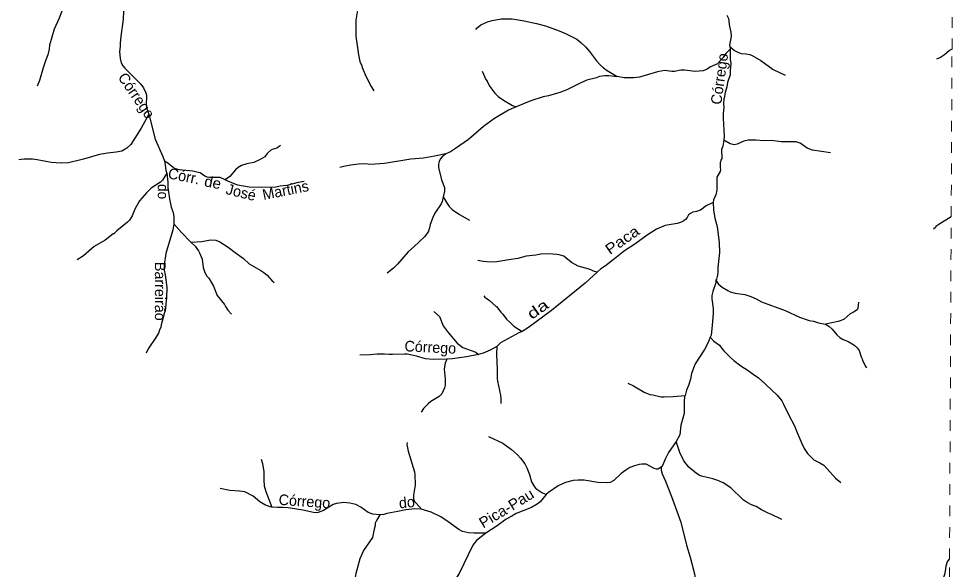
# Model space of a CAD drawing. Extents: x 551.6 to 577.6, y 7567 to 7594.7.
# Drawn here: x 568.78 to 577.56, y 7579.74 to 7584.89 of the extents above; entities that cross this region are included whole.
import ezdxf
from ezdxf.enums import TextEntityAlignment as Align

# ---------------------------------------------------------------- set-up
doc = ezdxf.new("R2010")
doc.units = 0
doc.header["$LTSCALE"] = 0.04
doc.linetypes.add('SHORT_DASHED', pattern=[2.7, 1.5, -1.2])
doc.layers.add('53', color=7, linetype='SHORT_DASHED', lineweight=13)
doc.layers.add('7', color=7, linetype='Continuous', lineweight=25)
doc.layers.add('61', color=7, linetype='Continuous')

msp = doc.modelspace()

# ---------------------------------------------------------------- linework, layer by layer
at = {"layer": '53'}
msp.add_lwpolyline([(577.4204, 7566.9518), (577.4226, 7567.3928), (577.4384, 7570.6314), (577.4446, 7571.9213), (577.4462, 7572.242), (577.4659, 7576.2813), (577.4696, 7577.0412), (577.4755, 7578.252), (577.4832, 7579.8317), (577.4989, 7583.0336), (577.5065, 7584.6034), (577.518, 7586.9644), (577.5184, 7587.0352), (577.519, 7587.1599), (577.5202, 7587.417), (577.5286, 7589.1281), (577.5292, 7589.2596), (577.5446, 7592.4063), (577.549, 7593.3187), (577.5554, 7594.6251)], dxfattribs=at)
at = {"layer": '7'}
for points in [[(571.9926, 7585.1972), (571.9443, 7584.9686), (571.9306, 7584.8736), (571.929, 7584.7256), (571.9547, 7584.5501), (571.9676, 7584.4873), (571.9861, 7584.4479), (571.9893, 7584.4326), (572.0264, 7584.3441), (572.0738, 7584.2547), (572.0964, 7584.2129)], [(569.7609, 7585.0958), (569.7528, 7584.8849), (569.7303, 7584.7207), (569.7246, 7584.6612), (569.7246, 7584.6274), (569.7182, 7584.5823), (569.723, 7584.5147), (569.7335, 7584.4761), (569.7496, 7584.4471), (569.7673, 7584.4237), (569.9162, 7584.2749), (569.9435, 7584.2411), (569.9653, 7584.1928), (569.9693, 7584.1735), (569.9717, 7584.1541), (569.9661, 7584.0898), (569.9741, 7584.0447), (569.9933, 7583.9944)], [(569.179, 7584.9573), (569.1548, 7584.8929), (569.1082, 7584.7915), (569.0631, 7584.6402), (569.0599, 7584.6032), (569.0486, 7584.5485), (569.0293, 7584.5034), (569.0027, 7584.4278), (568.9689, 7584.3087), (568.9488, 7584.258)], [(573.0525, 7584.7875), (573.0654, 7584.8028), (573.1, 7584.8293), (573.1595, 7584.8575), (573.2046, 7584.872), (573.2883, 7584.8865), (573.3913, 7584.8865), (573.504, 7584.8688), (573.6183, 7584.843), (573.702, 7584.8205), (573.8324, 7584.7746), (573.8967, 7584.7473), (573.9957, 7584.6958), (574.0344, 7584.6652), (574.0778, 7584.6233), (574.1148, 7584.5807), (574.1816, 7584.4929)], [(575.3989, 7584.9221), (575.4146, 7584.8913), (575.4194, 7584.8688), (575.421, 7584.835), (575.4266, 7584.8012), (575.4379, 7584.761), (575.4419, 7584.7223), (575.425, 7584.6419), (575.427, 7584.6289), (575.4307, 7584.6044)], [(575.427, 7584.6289), (575.4709, 7584.5911), (575.5096, 7584.5702), (575.5353, 7584.563), (575.5804, 7584.5597), (575.6142, 7584.5525), (575.6367, 7584.5428), (575.7188, 7584.4978), (575.8338, 7584.4124), (575.9466, 7584.3602)], [(575.4307, 7584.6044), (575.3912, 7584.563), (575.3661, 7584.5249), (575.3132, 7584.4664), (575.248, 7584.4374), (575.2166, 7584.4157), (575.178, 7584.4004), (575.1039, 7584.394), (575.0041, 7584.4068), (574.9703, 7584.4068), (574.9092, 7584.394), (574.8866, 7584.394), (574.819, 7584.4036), (574.7514, 7584.3907), (574.5824, 7584.3408), (574.5261, 7584.336), (574.4392, 7584.3344), (574.3742, 7584.3461)], [(575.4307, 7584.6044), (575.4323, 7584.505), (575.4387, 7584.4761), (575.4355, 7584.4278)], [(577.5065, 7584.6034), (577.4829, 7584.5895), (577.4354, 7584.5493), (577.3992, 7584.5243), (577.363, 7584.5083)], [(574.1816, 7584.4929), (574.2162, 7584.4551), (574.2476, 7584.4286), (574.2814, 7584.4036), (574.3742, 7584.3461)], [(573.1104, 7584.3964), (573.145, 7584.3199), (573.1563, 7584.3046), (573.1563, 7584.2998), (573.1837, 7584.2523), (573.2303, 7584.1896), (573.2601, 7584.1614), (573.3092, 7584.1244), (573.3945, 7584.0769), (573.4294, 7584.0619)], [(574.3742, 7584.3461), (574.349, 7584.3457), (574.2975, 7584.3537), (574.2589, 7584.3537), (574.2074, 7584.3457), (574.1816, 7584.336), (574.0915, 7584.3119), (574.0263, 7584.2845), (573.9032, 7584.2225), (573.8388, 7584.196), (573.7326, 7584.1654), (573.681, 7584.1573), (573.5652, 7584.1203), (573.4294, 7584.0619)], [(575.4355, 7584.4278), (575.4299, 7584.4085), (575.4299, 7584.3634), (575.4057, 7584.2918), (575.4001, 7584.2507), (575.384, 7584.196), (575.3759, 7584.1429), (575.3727, 7584.1397), (575.3695, 7584.0898), (575.3711, 7584.056), (575.3647, 7583.9996), (575.3647, 7583.9578), (575.3759, 7583.7888), (575.3733, 7583.75)], [(569.9933, 7583.9944), (569.9218, 7583.8644), (569.8228, 7583.7099), (569.7858, 7583.6753), (569.7391, 7583.6495), (569.6876, 7583.6382), (569.6072, 7583.6302), (569.5315, 7583.6165), (569.3802, 7583.5739), (569.2402, 7583.5393), (569.171, 7583.5368), (569.0776, 7583.5417), (568.9488, 7583.5682), (568.9038, 7583.5731)], [(569.9933, 7583.9944), (570.053, 7583.7614), (570.1238, 7583.5972), (570.1386, 7583.5553)], [(573.4294, 7584.0619), (573.3575, 7584.031), (573.2279, 7583.9553), (573.1249, 7583.8789)], [(573.1249, 7583.8789), (572.9825, 7583.759), (572.8626, 7583.672), (572.8154, 7583.6437), (572.7703, 7583.6234)], [(575.3733, 7583.75), (575.3623, 7583.6954), (575.3502, 7583.6648), (575.3518, 7583.5787), (575.3454, 7583.569), (575.3389, 7583.5401), (575.3389, 7583.491)], [(576.3683, 7583.6334), (576.2017, 7583.6584), (576.1518, 7583.6777), (576.0874, 7583.7227), (576.0488, 7583.7372), (575.9071, 7583.7348), (575.817, 7583.7469), (575.7494, 7583.7461), (575.6721, 7583.7517), (575.5981, 7583.7501), (575.5595, 7583.7421), (575.4951, 7583.7147), (575.4693, 7583.7083), (575.4307, 7583.7179), (575.3733, 7583.75)], [(571.2256, 7583.7018), (571.1894, 7583.6769), (571.1475, 7583.6648), (571.1347, 7583.6576), (571.1008, 7583.6278), (571.0767, 7583.5964), (571.0349, 7583.569), (570.9737, 7583.5433), (570.9093, 7583.5288), (570.861, 7583.5135), (570.8288, 7583.4966), (570.8023, 7583.4725), (570.7491, 7583.4113), (570.7053, 7583.3808)], [(568.9038, 7583.5731), (568.8249, 7583.5723), (568.7758, 7583.5682)], [(570.1386, 7583.5553), (570.1463, 7583.52), (570.1528, 7583.4668), (570.1613, 7583.4419)], [(570.2212, 7583.4966), (570.1713, 7583.5352), (570.1386, 7583.5553)], [(572.7703, 7583.6234), (572.6638, 7583.6004), (572.5608, 7583.5835), (572.4449, 7583.5731), (572.197, 7583.5336), (572.1101, 7583.5256), (572.0586, 7583.5248), (572.0199, 7583.5296), (571.9556, 7583.5264), (571.8815, 7583.5167), (571.8171, 7583.5046), (571.7793, 7583.4942)], [(572.7703, 7583.6234), (572.7354, 7583.594), (572.7185, 7583.5731), (572.7088, 7583.5505), (572.704, 7583.528), (572.7032, 7583.4942), (572.7314, 7583.3815), (572.7571, 7583.3091), (572.7587, 7583.2753), (572.7468, 7583.2204)], [(570.7053, 7583.3808), (570.6614, 7583.4016), (570.56, 7583.4032), (570.5375, 7583.4065), (570.515, 7583.4145), (570.4739, 7583.4443), (570.4554, 7583.4499), (570.4039, 7583.462), (570.2767, 7583.4741), (570.2429, 7583.4845), (570.2212, 7583.4966)], [(575.3389, 7583.491), (575.3405, 7583.4797), (575.3373, 7583.4572), (575.3075, 7583.4057), (575.3051, 7583.3815), (575.3067, 7583.285), (575.2955, 7583.2399), (575.2761, 7583.1932), (575.2727, 7583.168)], [(570.1613, 7583.4419), (570.119, 7583.3775), (570.1029, 7583.359), (570.0144, 7583.3018), (569.9709, 7583.2592), (569.9041, 7583.1836), (569.8623, 7583.1047), (569.8365, 7583.0419), (569.8116, 7583.0041), (569.7939, 7582.9855), (569.6924, 7582.9027), (569.6651, 7582.8753), (569.6603, 7582.8745), (569.583, 7582.8157), (569.4816, 7582.7578), (569.381, 7582.6685), (569.3214, 7582.6323)], [(570.1613, 7583.4419), (570.1697, 7583.359), (570.1705, 7583.3075), (570.185, 7583.2029), (570.2019, 7583.1256), (570.2212, 7583.0741), (570.2276, 7583.0355), (570.2277, 7582.9696)], [(571.4445, 7583.3638), (571.3906, 7583.3558), (571.2844, 7583.3284), (571.22, 7583.3212), (571.1813, 7583.3131), (571.0494, 7583.3075), (570.9302, 7583.3131), (570.8256, 7583.3308), (570.7226, 7583.3694), (570.7053, 7583.3808)], [(572.7468, 7583.2204), (572.7378, 7583.1787), (572.7273, 7583.1562), (572.6694, 7583.0677), (572.6485, 7583.029), (572.6251, 7582.9614), (572.6195, 7582.9325)], [(572.7468, 7583.2204), (572.7829, 7583.1578), (572.8038, 7583.1304), (572.8312, 7583.1031), (572.8996, 7583.0548), (572.9913, 7583.0033)], [(575.2727, 7583.168), (575.2053, 7583.1369), (575.1538, 7583.0958), (575.1152, 7583.0837), (575.0822, 7583.0773), (575.0605, 7583.066), (575.0419, 7583.0516), (575.0299, 7583.029), (575.0146, 7583.0105), (574.9969, 7582.996), (574.9671, 7582.9799), (574.9349, 7582.9711), (574.8239, 7582.9526), (574.7426, 7582.9172), (574.654, 7582.8616), (574.5406, 7582.7779), (574.4424, 7582.7143), (574.3635, 7582.654)], [(575.2727, 7583.168), (575.2745, 7583.0999), (575.289, 7583.0226), (575.3083, 7582.9437), (575.3293, 7582.7892), (575.3309, 7582.6991), (575.3164, 7582.559), (575.3148, 7582.5091), (575.3083, 7582.4753)], [(577.4989, 7583.0336), (577.3847, 7582.9638), (577.3558, 7582.9421), (577.3509, 7582.9332), (577.334, 7582.9172)], [(570.2277, 7582.9696), (570.2164, 7582.9115), (570.2043, 7582.8697)], [(570.2277, 7582.9696), (570.2969, 7582.8866), (570.3868, 7582.7977)], [(570.2043, 7582.8697), (570.1528, 7582.6894), (570.1351, 7582.5848), (570.1375, 7582.5365), (570.1463, 7582.4914), (570.1608, 7582.3739), (570.1592, 7582.2774), (570.1504, 7582.221), (570.1471, 7582.1727), (570.1077, 7582.0246), (570.1037, 7582.0005), (570.0932, 7581.9731)], [(572.6195, 7582.9325), (572.6082, 7582.9003), (572.5736, 7582.8503), (572.473, 7582.7538), (572.4183, 7582.7063), (572.3201, 7582.5896), (572.2807, 7582.5526), (572.2219, 7582.5075)], [(570.3868, 7582.7977), (570.4876, 7582.8029), (570.5697, 7582.8182), (570.618, 7582.8157), (570.6582, 7582.8005), (570.7347, 7582.7514), (570.8007, 7582.699), (570.8779, 7582.6443), (570.931, 7582.5936), (571.0413, 7582.5325), (571.0695, 7582.5123), (571.0984, 7582.4882), (571.1435, 7582.4391), (571.166, 7582.419)], [(570.3868, 7582.7977), (570.4248, 7582.7602), (570.4562, 7582.7168), (570.4675, 7582.6958), (570.49, 7582.6379), (570.5021, 7582.5606), (570.5149, 7582.522), (570.5335, 7582.4834), (570.5528, 7582.4592), (570.5978, 7582.3852), (570.6308, 7582.2983), (570.7001, 7582.2146), (570.7097, 7582.1937), (570.7322, 7582.1606), (570.7669, 7582.122)], [(574.1871, 7582.5159), (574.1623, 7582.522), (574.1124, 7582.5437), (574.0086, 7582.5727), (573.9474, 7582.6081), (573.8742, 7582.6652), (573.8324, 7582.6797), (573.8098, 7582.683), (573.7358, 7582.6878), (573.6585, 7582.6862), (573.6134, 7582.6765), (573.5233, 7582.6652), (573.4444, 7582.6427), (573.3607, 7582.6331), (573.2481, 7582.6129), (573.1901, 7582.6089), (573.1193, 7582.617), (573.0718, 7582.625)], [(574.3635, 7582.654), (574.2661, 7582.5767), (574.2202, 7582.5461), (574.1871, 7582.5159)], [(574.1871, 7582.5159), (574.0746, 7582.4133), (573.7583, 7582.1582), (573.5458, 7581.9989), (573.4851, 7581.9612), (573.4541, 7581.9482)], [(575.2978, 7582.4415), (575.2979, 7582.4158), (575.2689, 7582.3369), (575.26, 7582.2983), (575.2584, 7582.2677), (575.2713, 7582.1776), (575.2713, 7582.1325), (575.2633, 7582.0182), (575.252, 7581.9281), (575.2436, 7581.9075)], [(575.3083, 7582.4753), (575.3043, 7582.4512), (575.2978, 7582.4415)], [(575.2978, 7582.4415), (575.322, 7582.4045), (575.355, 7582.3771), (575.4081, 7582.3441), (575.4323, 7582.3329), (575.4774, 7582.32), (575.5675, 7582.3079), (575.6254, 7582.2886), (575.6753, 7582.2669), (575.7236, 7582.2387), (575.9458, 7582.1566), (576.081, 7582.0938), (576.1711, 7582.0649), (576.2113, 7582.0568), (576.2578, 7582.0428), (576.3231, 7582.0312)], [(573.1265, 7582.2959), (573.1362, 7582.2838), (573.1796, 7582.2508), (573.2432, 7582.1936), (573.2465, 7582.1936), (573.2859, 7582.1421), (573.3044, 7582.1236), (573.3382, 7582.0762), (573.3752, 7582.0407), (573.4074, 7582.0118), (573.4851, 7581.9612)], [(576.6331, 7582.2347), (576.6266, 7582.1808), (576.6186, 7582.163), (576.5864, 7582.1421), (576.5542, 7582.126), (576.4986, 7582.0769), (576.4697, 7582.0633), (576.4415, 7582.0552), (576.3231, 7582.0312)], [(572.6598, 7582.1478), (572.7104, 7582.1019), (572.7475, 7582.015), (572.7933, 7581.9522), (572.8762, 7581.8524), (572.9294, 7581.8113), (573.0533, 7581.7671), (573.0779, 7581.7465)], [(576.3231, 7582.0312), (576.3554, 7582.0101), (576.386, 7581.9828)], [(576.386, 7581.9828), (576.4294, 7581.9289), (576.456, 7581.9039), (576.4818, 7581.8894), (576.5365, 7581.8669), (576.588, 7581.8363), (576.6041, 7581.825), (576.6194, 7581.8089), (576.6395, 7581.7848), (576.6556, 7581.7253), (576.6668, 7581.7051), (576.6701, 7581.6898), (576.699, 7581.6319), (576.7079, 7581.6198)], [(570.0932, 7581.9731), (570.0828, 7581.9442), (570.0594, 7581.9047), (569.9854, 7581.7977), (569.9677, 7581.7582)], [(573.4541, 7581.9482), (573.2841, 7581.8536), (573.2468, 7581.821)], [(575.2436, 7581.9075), (575.2238, 7581.8589), (575.1916, 7581.7929), (575.1023, 7581.6577), (575.0685, 7581.5675), (575.0596, 7581.5144), (575.042, 7581.4565)], [(575.2436, 7581.9075), (575.2786, 7581.8709), (575.3309, 7581.8331), (575.3534, 7581.8009), (575.3719, 7581.7808), (575.4339, 7581.7172), (575.4653, 7581.6898), (575.5313, 7581.6399), (575.6005, 7581.5957), (575.6464, 7581.5611), (575.6971, 7581.5281), (575.755, 7581.4758), (575.7671, 7581.4605), (575.8717, 7581.3663), (575.9135, 7581.3116), (575.9313, 7581.281), (575.9787, 7581.1796), (576.0327, 7581.0782), (576.0552, 7581.0235)], [(573.2468, 7581.821), (573.1869, 7581.7856), (573.1193, 7581.7598), (573.1192, 7581.7574), (573.0779, 7581.7465)], [(573.2468, 7581.821), (573.2448, 7581.7494), (573.2529, 7581.6045), (573.2521, 7581.5224), (573.2545, 7581.4951), (573.2818, 7581.3663), (573.2859, 7581.3325), (573.2843, 7581.2987), (573.2867, 7581.2866)], [(572.2726, 7581.7462), (572.2405, 7581.7446), (572.197, 7581.7494), (572.1294, 7581.7502), (572.0618, 7581.7429), (571.9676, 7581.7381)], [(572.7812, 7581.703), (572.6541, 7581.6979), (572.5801, 7581.7051), (572.498, 7581.7301), (572.4079, 7581.7486), (572.3853, 7581.7502), (572.2726, 7581.7462)], [(573.0779, 7581.7465), (572.9632, 7581.7244), (572.833, 7581.7051), (572.7812, 7581.703)], [(572.7812, 7581.703), (572.766, 7581.6657), (572.7571, 7581.6319), (572.7563, 7581.6094), (572.7652, 7581.516), (572.766, 7581.4581), (572.7587, 7581.4355), (572.7322, 7581.3776), (572.7089, 7581.3526), (572.6316, 7581.3059), (572.605, 7581.2842), (572.5615, 7581.2408), (572.5398, 7581.2078)], [(574.4738, 7581.479), (574.5277, 7581.4524), (574.6259, 7581.3937), (574.679, 7581.3711), (574.708, 7581.3679), (574.7868, 7581.3502), (574.8126, 7581.3494), (574.8979, 7581.3518), (575.0089, 7581.3629)], [(575.042, 7581.4565), (575.0234, 7581.413), (575.0089, 7581.3629)], [(575.0089, 7581.3629), (575.0041, 7581.3567), (574.9993, 7581.3019), (575.0009, 7581.1941), (574.9711, 7581.0846), (574.9607, 7580.9945), (574.9244, 7580.9318)], [(576.0552, 7581.0235), (576.1019, 7580.9124), (576.1244, 7580.8673), (576.1542, 7580.8198), (576.2129, 7580.7611), (576.2709, 7580.7321), (576.3063, 7580.7088), (576.3401, 7580.6774), (576.4174, 7580.5897), (576.4665, 7580.5486)], [(572.4079, 7580.9213), (572.4078, 7580.9028), (572.4175, 7580.8416), (572.477, 7580.6484), (572.4811, 7580.6227), (572.4835, 7580.5237), (572.4674, 7580.4295), (572.4698, 7580.3909), (572.4786, 7580.3716), (572.5347, 7580.3105), (572.5402, 7580.2987)], [(573.1716, 7580.9776), (573.3036, 7580.9156), (573.3841, 7580.8569), (573.4428, 7580.8062), (573.471, 7580.7764), (573.5104, 7580.7241), (573.5297, 7580.6855), (573.5547, 7580.6227), (573.574, 7580.5551), (573.6005, 7580.5068), (573.6126, 7580.4923), (573.64, 7580.4722), (573.6682, 7580.4553), (573.7096, 7580.4363)], [(574.9244, 7580.9318), (574.8544, 7580.8287), (574.8255, 7580.7724), (574.7981, 7580.708), (574.786, 7580.6903)], [(575.046, 7580.6911), (575.0081, 7580.737), (574.9953, 7580.7579), (574.9607, 7580.8303), (574.9244, 7580.9318)], [(571.0445, 7580.7651), (571.055, 7580.7273), (571.0695, 7580.6484), (571.067, 7580.5712), (571.0711, 7580.5181), (571.0872, 7580.4633), (571.1419, 7580.3179)], [(574.786, 7580.6903), (574.7547, 7580.6742), (574.7434, 7580.6742), (574.7192, 7580.679), (574.6452, 7580.72), (574.6033, 7580.7208), (574.5808, 7580.7176), (574.5357, 7580.7048), (574.4939, 7580.687), (574.4537, 7580.6645), (574.4102, 7580.6323), (574.3418, 7580.5663), (574.3088, 7580.5486), (574.2863, 7580.5454), (574.1945, 7580.5486), (574.0657, 7580.5695), (574.0094, 7580.5712), (573.9627, 7580.5679), (573.8903, 7580.5478), (573.8227, 7580.5156), (573.7325, 7580.4561), (573.7096, 7580.4363)], [(574.786, 7580.6903), (574.7852, 7580.6629), (574.7957, 7580.6291), (574.8255, 7580.5615), (574.8818, 7580.4167)], [(575.9144, 7580.201), (575.8178, 7580.25), (575.7864, 7580.2621), (575.7244, 7580.2927), (575.6729, 7580.3241), (575.6303, 7580.3394), (575.59, 7580.3611), (575.5538, 7580.3869), (575.4379, 7580.4971), (575.3647, 7580.5454), (575.3148, 7580.5671), (575.2681, 7580.5824), (575.1619, 7580.6082), (575.1426, 7580.6154), (575.1152, 7580.6323), (575.046, 7580.6911)], [(571.1419, 7580.3179), (571.1266, 7580.3192), (571.0767, 7580.3402), (571.0324, 7580.3683), (570.9673, 7580.419), (570.8916, 7580.4609), (570.8417, 7580.4681), (570.75, 7580.4738), (570.6606, 7580.4907)], [(573.7096, 7580.4363), (573.6529, 7580.3683), (573.6247, 7580.345), (573.5732, 7580.3128), (573.4299, 7580.2573), (573.3873, 7580.2339), (573.3366, 7580.205), (573.2513, 7580.143), (573.1451, 7580.075)], [(574.8818, 7580.4167), (574.9687, 7580.1784), (575.0234, 7579.9611), (575.0572, 7579.8501), (575.0967, 7579.6939), (575.1136, 7579.5732), (575.1152, 7579.4944), (575.1196, 7579.461)], [(571.4324, 7580.2887), (571.2972, 7580.3104), (571.2425, 7580.3152), (571.1961, 7580.3134), (571.1419, 7580.3179)], [(572.1544, 7580.2464), (572.0892, 7580.2525), (572.0433, 7580.2669), (571.9749, 7580.3176), (571.9298, 7580.341), (571.8735, 7580.3539), (571.8171, 7580.3603), (571.7495, 7580.353), (571.7173, 7580.3434), (571.6272, 7580.2871), (571.5757, 7580.2661), (571.5644, 7580.2645), (571.5322, 7580.2677), (571.4324, 7580.2887)], [(572.1544, 7580.2464), (572.1221, 7580.1929), (572.1109, 7580.1663), (572.1101, 7580.1462), (572.1004, 7580.1124), (572.0859, 7580.0336), (572.0014, 7579.9128), (571.9676, 7579.834), (571.9298, 7579.6972), (571.9201, 7579.64)], [(572.5402, 7580.2987), (572.4803, 7580.3015), (572.3982, 7580.2935), (572.3209, 7580.2758), (572.2179, 7580.2573), (572.1909, 7580.2495), (572.1544, 7580.2464)], [(573.1451, 7580.075), (573.0372, 7580.0738), (572.9841, 7580.077), (572.9278, 7580.0899), (572.8915, 7580.1084), (572.7933, 7580.1816), (572.7249, 7580.2259), (572.6348, 7580.2702), (572.5402, 7580.2987)], [(573.1451, 7580.075), (573.0573, 7580.0054), (573.0251, 7579.9611), (572.8972, 7579.6955), (572.8778, 7579.6682), (572.8263, 7579.5813), (572.7764, 7579.5201), (572.7394, 7579.463)], [(577.4832, 7579.8317), (577.4757, 7579.8275), (577.4604, 7579.805), (577.4475, 7579.7664), (577.4427, 7579.7181), (577.4354, 7579.6859), (577.3895, 7579.5443), (577.3614, 7579.4774), (577.3517, 7579.4622), (577.3236, 7579.4348), (577.289, 7579.3744), (577.2535, 7579.339), (577.2238, 7579.3157), (577.1666, 7579.2786), (577.1232, 7579.2577)]]:
    msp.add_lwpolyline(points, dxfattribs=at)

# ---------------------------------------------------------------- texts
at = {"layer": '61'}
for s, rotation, p in [('Córrego', 82.134, (575.38, 7584.3186)), ('Córrego', 304.6, (569.8353, 7584.1402)), ('Córr.', 348.474, (570.3111, 7583.3659)), ('José', 346.245, (570.8442, 7583.2152)), ('Martins', 11.31, (571.2808, 7583.2338)), ('Barreirão', 270, (570.0494, 7582.3372)), ('Córrego', 357.245, (572.6239, 7581.7644)), ('Córrego', 355.996, (571.4453, 7580.3227)), ('do', 5.69, (572.4109, 7580.3126))]:
    msp.add_text(s, height=0.1, rotation=rotation, dxfattribs=at).set_placement(p, align=Align.CENTER)
for s, rotation, width, p in [('de', 348.706, 1.05, (570.5815, 7583.3066)), ('do', 270, 0.95, (570.0764, 7583.2702)), ('Paca', 35.24, 1.15, (574.4498, 7582.7761)), ('da', 35.24, 1.4, (573.6598, 7582.129)), ('Pica-Pau', 31.178, 1.05, (573.3637, 7580.2647))]:
    msp.add_text(s, height=0.1, rotation=rotation, dxfattribs=dict(at, width=width)).set_placement(p, align=Align.CENTER)

doc.saveas('drawing.dxf')
